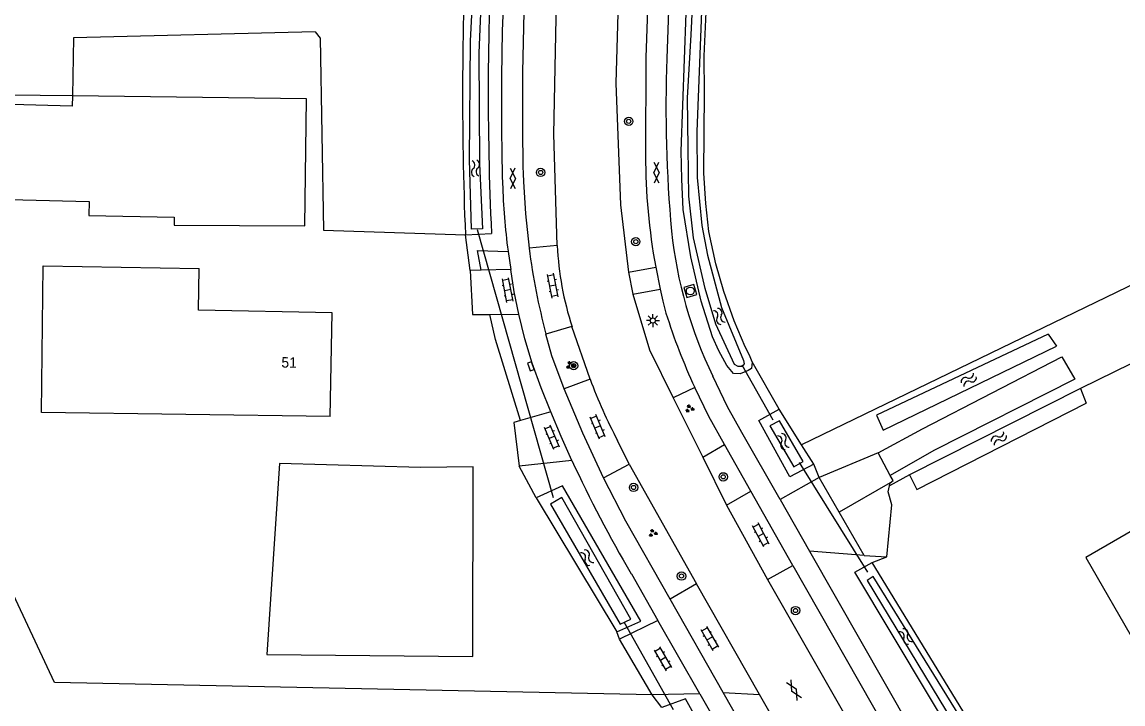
# Model space of a CAD drawing. Extents: x 134297 to 137000, y 403500 to 406000.
# Drawn here: x 136655.3 to 136760.9, y 403757 to 403822.5 of the extents above; entities that cross this region are included whole.
import ezdxf

# ---------------------------------------------------------------- set-up
doc = ezdxf.new("R2010")
doc.units = 0
for name, color, linetype in [('gg-afsc-draadraster', 7, 'Continuous'), ('gg-afsc-lijn draadraster', 7, 'Continuous'), ('gg-anno-huisnummerreeks BGT', 7, 'Continuous'), ('gg-bbg-bijgebouw', 7, 'Continuous'), ('gg-bbg-gedigitaliseerde bebouwing', 7, 'Continuous'), ('gg-bbg-hoofdgebouw', 7, 'Continuous'), ('gg-knt-bronhoudergrens', 7, 'Continuous'), ('gg-knt-onverhard', 7, 'Continuous'), ('gg-knt-verharding', 7, 'Continuous'), ('gg-knt-verharding nz', 7, 'Continuous'), ('gg-kntw-bovenkant insteek waterloop', 7, 'Continuous'), ('gg-kntw-waterlijn', 7, 'Continuous'), ('gg-kwrk-duiker nz buis', 7, 'Continuous'), ('gt-grn-groengrens', 7, 'Continuous'), ('gt-grn-vlakafsluiter', 7, 'Continuous'), ('gt-grn-weggrens', 7, 'Continuous'), ('gt-symb-boom', 7, 'Continuous'), ('gt-symb-gesloten verharding', 7, 'Continuous'), ('gt-symb-groenvak', 7, 'Continuous'), ('gt-symb-klinker verharding', 7, 'Continuous'), ('gt-symb-kolk', 7, 'Continuous'), ('gt-symb-lichtmast', 7, 'Continuous'), ('gt-symb-rioolschacht', 7, 'Continuous'), ('gt-symb-watersymbool', 7, 'Continuous')]:
    doc.layers.add(name, color=color, linetype=linetype)

# ---------------------------------------------------------------- blocks, each defined once
blk = doc.blocks.new('gt0-WA')
at = {"layer": 'gt-symb-watersymbool'}
for centre, start, end in [((-0.32, 0.02), 28.0725, 151.9275), ((0.43, 0.42), 208.0725, 331.9275), ((-0.32, -0.43), 28.0725, 151.9275), ((0.43, -0.03), 208.0725, 331.9275)]:
    blk.add_arc(centre, 0.425, start, end, dxfattribs=at)
blk = doc.blocks.new('gt0-KL1')
at = {"layer": 'gt-symb-klinker verharding'}
for p, q in [((-1.15, 0.3), (1.15, 0.3)), ((-1, -0.3), (-1, 0.3)), ((-0.5, 0.3), (-0.5, 0.45)), ((0, -0.3), (0, 0.3)), ((0.5, 0.3), (0.5, 0.45)), ((1, -0.3), (1, 0.3)), ((-1.15, -0.3), (1.15, -0.3)), ((-0.5, -0.45), (-0.5, -0.3)), ((0.5, -0.45), (0.5, -0.3))]:
    blk.add_line(p, q, dxfattribs=at)
blk = doc.blocks.new('gt0-GESVH1')
at = {"layer": 'gt-symb-gesloten verharding'}
for p, q in [((-0.99, -0.26), (0.01, 0.24)), ((0.01, -0.26), (-0.99, 0.24)), ((0.01, 0.24), (1.01, -0.26)), ((1.01, 0.24), (0.01, -0.26))]:
    blk.add_line(p, q, dxfattribs=at)
blk = doc.blocks.new('gt0-BOOM')
at = {"layer": 'gt-symb-boom'}
for radius in [0.4, 0.2]:
    blk.add_circle((0, 0), radius, dxfattribs=at)
blk = doc.blocks.new('gt0-GRVAK')
at = {"layer": 'gt-symb-groenvak'}
for p, q in [((-0.11, 0.19), (-0.23, 0.24)), ((-0.18, 0.15), (0.09, 0.15)), ((-0.09, 0.21), (-0.16, 0.32)), ((-0.05, 0.21), (-0.05, 0.39)), ((0, 0.21), (0.06, 0.32)), ((0.01, 0.19), (0.13, 0.24)), ((0.26, -0.05), (0.2, 0.06)), ((0.3, -0.05), (0.3, 0.13)), ((0.35, -0.05), (0.41, 0.06)), ((-0.24, -0.23), (-0.36, -0.18)), ((-0.32, -0.26), (-0.05, -0.26)), ((-0.23, -0.21), (-0.29, -0.09)), ((-0.18, -0.2), (-0.18, -0.02)), ((-0.14, -0.21), (-0.07, -0.09)), ((-0.12, -0.23), (0, -0.18)), ((0.24, -0.07), (0.12, -0.02)), ((0.17, -0.11), (0.44, -0.11)), ((0.37, -0.07), (0.49, -0.02))]:
    blk.add_line(p, q, dxfattribs=at)
blk = doc.blocks.new('gt0-LMAST')
at = {"layer": 'gt-symb-lichtmast'}
for p, q in [((-0.18, 0.17), (-0.45, 0.44)), ((-0.01, 0.25), (-0.01, 0.62)), ((0.17, 0.17), (0.44, 0.44)), ((-0.26, 0), (-0.63, 0)), ((-0.18, -0.18), (-0.45, -0.45)), ((-0.01, -0.25), (-0.01, -0.63)), ((0.44, -0.45), (0.17, -0.18)), ((0.24, 0), (0.62, 0))]:
    blk.add_line(p, q, dxfattribs=at)
blk.add_circle((-0.01, 0), 0.25, dxfattribs=at)
blk = doc.blocks.new('gt0-RS')
at = {"layer": 'gt-symb-rioolschacht'}
blk.add_lwpolyline([(-0.5, -0.5), (0.5, -0.5), (0.5, 0.5), (-0.5, 0.5)], close=True, dxfattribs=at)
blk.add_circle((0, 0), 0.375, dxfattribs=at)
blk = doc.blocks.new('gt0-KOLK')
at = {"layer": 'gt-symb-kolk'}
blk.add_lwpolyline([(0, 0), (0.38, 0), (0.38, 0.4), (-0.38, 0.4), (-0.38, 0), (0, 0)], dxfattribs=at)

msp = doc.modelspace()

# ---------------------------------------------------------------- linework, layer by layer
at = {"layer": 'gg-afsc-draadraster'}
msp.add_lwpolyline([(136715.77, 403757.91), (136658.46, 403759.09), (136652.16, 403772.51), (136648.44, 403778.54), (136647.3, 403780.85), (136647.28, 403784.23), (136613.81, 403784.54), (136613.66, 403800.45)], dxfattribs=at)
at = {"layer": 'gg-afsc-lijn draadraster'}
msp.add_lwpolyline([(136715.77, 403757.91), (136658.46, 403759.09), (136652.16, 403772.51), (136648.44, 403778.54), (136647.3, 403780.85), (136647.28, 403784.23), (136613.81, 403784.54), (136613.66, 403800.45)], dxfattribs=at)
at = {"layer": 'gg-bbg-bijgebouw'}
msp.add_lwpolyline([(136660.18, 403815.37), (136660.16, 403814.39), (136640.38, 403814.94), (136640.14, 403805.8), (136661.78, 403805.25), (136661.75, 403803.89), (136669.93, 403803.75), (136669.93, 403802.98), (136682.47, 403802.91), (136682.61, 403815.1), (136660.18, 403815.37)], dxfattribs=at)
at = {"layer": 'gg-bbg-gedigitaliseerde bebouwing'}
msp.add_lwpolyline([(136684.88, 403784.61), (136657.21, 403784.99), (136657.38, 403799.06), (136672.32, 403798.83)], dxfattribs=at)
at = {"layer": 'gg-bbg-hoofdgebouw'}
for points in [[(136684.88, 403784.61), (136685.09, 403794.57), (136672.25, 403794.83), (136672.32, 403798.83)], [(136765.89, 403776.04), (136757.34, 403771.09)], [(136757.34, 403771.09), (136762.17, 403762.72)]]:
    msp.add_lwpolyline(points, dxfattribs=at)
at = {"layer": 'gg-knt-bronhoudergrens'}
for p, q in [((136792.85, 403805.05), (136756.81, 403787.3)), ((136716.69, 403756.7), (136715.77, 403757.91))]:
    msp.add_line(p, q, dxfattribs=at)
for points in [[(136859.35, 403844.51), (136842.84, 403836.67), (136782.41, 403807.25), (136730.09, 403781.89)], [(136683.44, 403821.51), (136660.29, 403820.93), (136660.18, 403815.37)], [(136683.44, 403821.51), (136683.93, 403820.9), (136684.26, 403802.49), (136697.85, 403802.03)], [(136660.18, 403815.37), (136613.5, 403815.87), (136613.66, 403800.45)], [(136698.55, 403761.6), (136698.6, 403779.78), (136693.55, 403779.71), (136680.02, 403780.1), (136678.81, 403761.79), (136698.55, 403761.6)]]:
    msp.add_lwpolyline(points, dxfattribs=at)
at = {"layer": 'gg-knt-onverhard'}
for points in [[(136737.41, 403781.13), (136741.69, 403783.43), (136755.04, 403790.34)], [(136756.27, 403788.19), (136742.76, 403781.36), (136738.58, 403778.95)]]:
    msp.add_lwpolyline(points, dxfattribs=at)
at = {"layer": 'gg-knt-verharding'}
for p, q in [((136701.94, 403800.46), (136702.21, 403798.71)), ((136706.66, 403801.02), (136703.95, 403800.76)), ((136699.35, 403798.64), (136698.32, 403798.62)), ((136702.21, 403798.71), (136699.35, 403798.64)), ((136713.5, 403798.47), (136716.1, 403798.95)), ((136713.5, 403798.47), (136713.9, 403796.36)), ((136716.1, 403798.95), (136716.53, 403796.83)), ((136713.9, 403796.36), (136716.53, 403796.83)), ((136700.18, 403794.41), (136702.96, 403794.45)), ((136708.07, 403793.24), (136705.56, 403792.51)), ((136709.8, 403788.21), (136708.07, 403793.24)), ((136709.8, 403788.21), (136707.33, 403787.27)), ((136717.78, 403786.42), (136720.6, 403780.72)), ((136706.04, 403785.05), (136703.14, 403784.24)), ((136713.54, 403780.06), (136712.44, 403782.32)), ((136725.23, 403777.44), (136722.68, 403781.92)), ((136737.41, 403781.13), (136731.78, 403778.78)), ((136738.58, 403778.95), (136737.41, 403781.13)), ((136708.06, 403780.4), (136703.01, 403779.84)), ((136711.08, 403778.75), (136713.54, 403780.06)), ((136713.54, 403780.06), (136720, 403768.55)), ((136720.6, 403780.72), (136722.89, 403776.1)), ((136731.78, 403778.78), (136728.04, 403776.64)), ((136733.7, 403775.44), (136731.78, 403778.78)), ((136738.52, 403777.97), (136738.59, 403778.25)), ((136722.89, 403776.1), (136725.23, 403777.44)), ((136729.23, 403770.34), (136725.23, 403777.44)), ((136722.89, 403776.1), (136726.83, 403768.98)), ((136728.04, 403776.64), (136730.84, 403771.71)), ((136736.09, 403771.29), (136733.7, 403775.44)), ((136736.09, 403771.29), (136730.84, 403771.71)), ((136730.84, 403771.71), (136776.48, 403691.56)), ((136736.09, 403771.29), (136738.25, 403771.14)), ((136713.76, 403769.53), (136716.31, 403765.06)), ((136726.83, 403768.98), (136729.23, 403770.34)), ((136729.23, 403770.34), (136774.89, 403690.26)), ((136720, 403768.55), (136717.47, 403767.09)), ((136726.04, 403757.96), (136720, 403768.55)), ((136726.83, 403768.98), (136773.23, 403687.76)), ((136722.56, 403758.14), (136717.47, 403767.09)), ((136716.31, 403765.06), (136712.62, 403763.27)), ((136720.33, 403758.01), (136716.31, 403765.06)), ((136715.77, 403757.91), (136712.62, 403763.27)), ((136720.33, 403758.01), (136715.77, 403757.91)), ((136720.33, 403758.01), (136726.27, 403747.62)), ((136727.22, 403749.95), (136722.56, 403758.14)), ((136722.56, 403758.14), (136726.04, 403757.96)), ((136729.82, 403751.34), (136726.04, 403757.96))]:
    msp.add_line(p, q, dxfattribs=at)
for points in [[(136721.41, 403912.31), (136717.59, 403830.93), (136717.16, 403818.97)], [(136716.39, 403911.3), (136715.66, 403893.27), (136714.5, 403868.42), (136712.83, 403835.52), (136712.27, 403816.6), (136712.72, 403804.92), (136713.5, 403798.47)], [(136719.32, 403911.12), (136715.57, 403830.99), (136715.14, 403819.05), (136715.13, 403809.67)], [(136706.66, 403801.02), (136706.33, 403811.7), (136706.78, 403834.02), (136708.07, 403859.85), (136709.6, 403889.61), (136710.13, 403901.36)], [(136703.41, 403807.16), (136703.6, 403804.05), (136703.95, 403800.76)], [(136698.32, 403798.62), (136698.53, 403794.4), (136700.18, 403794.41)], [(136702.96, 403794.45), (136702.54, 403796.57), (136702.21, 403798.71)], [(136713.9, 403796.36), (136715.5, 403791), (136717.78, 403786.42)], [(136716.53, 403796.83), (136716.79, 403795.68), (136717.08, 403794.54)], [(136706.04, 403785.05), (136705.12, 403787.38), (136704.24, 403789.73), (136703.54, 403792.07), (136702.96, 403794.45)], [(136707.33, 403787.27), (136706.14, 403790.43), (136705.56, 403792.51)], [(136728.04, 403776.64), (136724.35, 403783.09), (136722.99, 403785.54), (136721.57, 403788.48)], [(136722.68, 403781.92), (136721.19, 403784.63), (136719.84, 403787.41)], [(136711.08, 403778.75), (136709.1, 403783.01), (136707.33, 403787.27)], [(136703.14, 403784.24), (136702.48, 403784.05), (136703.01, 403779.84)], [(136708.06, 403780.4), (136707.03, 403782.71), (136706.04, 403785.05)], [(136738.59, 403778.25), (136738.85, 403778.47), (136738.58, 403778.95)], [(136717.47, 403767.09), (136713.22, 403774.58), (136711.08, 403778.75)], [(136738.74, 403776.15), (136738.39, 403777.4), (136738.52, 403777.97)]]:
    msp.add_lwpolyline(points, dxfattribs=at)
for centre, radius, start, end in [((136971.2, 403814.58), 269.9, 176.6428, 181.6149), ((136967.96, 403814.36), 264.65, 176.5525, 181.5588), ((136852.84, 403814.37), 135.76, 178.0569, 185.0551), ((136775.43, 403809.74), 60.31, 180.0674, 190.3118), ((136760.94, 403808.57), 59.55, 181.5356, 187.8242), ((136759.12, 403806.7), 41.73, 185.9058, 205.8839), ((136769.79, 403809.34), 66.39, 187.4264, 194.6855), ((136736.45, 403802.41), 29.82, 182.6771, 197.9196), ((136777.17, 403813.71), 63.08, 197.6933, 204.64), ((136753.2, 403804.11), 46.22, 200.1259, 208.1378), ((136817.02, 403830.52), 119.93, 204.7017, 210.5698)]:
    msp.add_arc(centre, radius, start, end, dxfattribs=at)
at = {"layer": 'gg-knt-verharding nz'}
msp.add_line((136738.59, 403778.25), (136733.7, 403775.44), dxfattribs=at)
at = {"layer": 'gg-kntw-bovenkant insteek waterloop'}
for p, q in [((136720.73, 403819.19), (136724.79, 403908.84)), ((136697.85, 403802.03), (136700.34, 403802.18)), ((136753.71, 403792.51), (136754.52, 403791.35)), ((136756.81, 403787.3), (136740.43, 403779.01)), ((136756.81, 403787.3), (136757.38, 403785.91)), ((136730.09, 403781.89), (136727.93, 403785.31)), ((136731.26, 403780.03), (136730.09, 403781.89)), ((136704.64, 403776.83), (136712.38, 403763.96)), ((136773.06, 403711.41), (136736.85, 403770.62))]:
    msp.add_line(p, q, dxfattribs=at)
for points in [[(136725.33, 403789.87), (136725.27, 403789.21), (136724.96, 403789.03), (136724.19, 403788.7), (136723.56, 403788.74), (136722.93, 403789.51), (136722.14, 403790.93), (136721.55, 403792.25), (136720.46, 403795.69), (136719.48, 403799.92), (136718.74, 403804.48), (136718.59, 403807.4), (136718.55, 403810.07), (136719.19, 403827.75), (136720.59, 403862.43), (136722.55, 403909.1), (136724.79, 403908.84)], [(136725.33, 403789.87), (136725.08, 403790.5), (136724.67, 403791.31), (136723.62, 403793.79), (136722.63, 403796.6), (136721.85, 403799.27), (136721.19, 403802.35), (136720.91, 403805.04), (136720.72, 403807.96), (136720.79, 403815.68), (136720.73, 403819.19)], [(136753.71, 403792.51), (136737.26, 403784.74), (136737.9, 403783.31), (136754.52, 403791.35)], [(136731.26, 403780.03), (136728.96, 403778.83), (136725.99, 403784.25), (136727.93, 403785.31)], [(136740.43, 403779.01), (136741.12, 403777.63), (136757.38, 403785.91)], [(136712.38, 403763.96), (136714.68, 403764.98), (136707.17, 403777.97), (136704.64, 403776.83)], [(136770.71, 403710.36), (136735.2, 403769.68), (136736.85, 403770.62)], [(136721.62, 403747.83), (136723.64, 403749.06), (136718.94, 403757.52), (136716.69, 403756.7)]]:
    msp.add_lwpolyline(points, dxfattribs=at)
for centre, radius, start, end in [((137024.36, 403815.32), 326.78, 176.9586, 182.3305), ((136998.83, 403815.71), 298.79, 176.8644, 182.5947)]:
    msp.add_arc(centre, radius, start, end, dxfattribs=at)
at = {"layer": 'gg-kntw-waterlijn'}
for points in [[(136723.76, 403897.15), (136722.29, 403869.58), (136720.03, 403811.97), (136720.07, 403807.54), (136720.53, 403802.93), (136721.05, 403800.08), (136722.39, 403795.09), (136724.51, 403790), (136724.57, 403789.68), (136724.38, 403789.43), (136724, 403789.4), (136723.64, 403789.6), (136721.87, 403793.46), (136720.84, 403796.91), (136719.72, 403801.77), (136719.28, 403805.76), (136719.21, 403810.35), (136719.13, 403815.19), (136719.5, 403821.23), (136720.27, 403836.93), (136723.22, 403908.16), (136724.21, 403908.11), (136723.76, 403897.15)], [(136698.42, 403802.6), (136698.25, 403809.26), (136698.35, 403820.64), (136702.6, 403902.6), (136703.67, 403902.54), (136702.34, 403883.74), (136700.88, 403852.52), (136699.76, 403833.95), (136699.14, 403819.49), (136699.2, 403808.86), (136699.49, 403802.61), (136698.42, 403802.6)], [(136727.04, 403783.72), (136729.33, 403779.78), (136730.24, 403780.31), (136727.97, 403784.2), (136727.04, 403783.72)], [(136706, 403776.21), (136712.7, 403764.71), (136713.71, 403765.17), (136707.09, 403776.84), (136706, 403776.21)], [(136736.37, 403768.88), (136752.13, 403742.87), (136760.69, 403728.96), (136771.19, 403711.08), (136771.85, 403711.47), (136757.42, 403735.78), (136746.08, 403754.48), (136736.96, 403769.26), (136736.37, 403768.88)]]:
    msp.add_lwpolyline(points, dxfattribs=at)
at = {"layer": 'gg-kwrk-duiker nz buis'}
for p, q in [((136706.31, 403776.8), (136699.02, 403802.52)), ((136724.35, 403789.56), (136727.33, 403784.29)), ((136736.45, 403769.68), (136729.89, 403780.22)), ((136717.81, 403756.47), (136713.07, 403764.89))]:
    msp.add_line(p, q, dxfattribs=at)
at = {"layer": 'gt-grn-groengrens'}
for p, q in [((136698.32, 403798.62), (136697.85, 403802.03)), ((136719.84, 403787.41), (136717.78, 403786.42)), ((136720.6, 403780.72), (136722.68, 403781.92)), ((136731.78, 403778.78), (136731.26, 403780.03)), ((136704.64, 403776.83), (136703.01, 403779.84)), ((136736.85, 403770.62), (136738.25, 403771.14)), ((136712.62, 403763.27), (136712.38, 403763.96))]:
    msp.add_line(p, q, dxfattribs=at)
for points in [[(136699.35, 403798.64), (136699.01, 403800.55), (136701.94, 403800.46)], [(136703.14, 403784.24), (136700.75, 403791.99), (136700.18, 403794.41)]]:
    msp.add_lwpolyline(points, dxfattribs=at)
at = {"layer": 'gt-grn-vlakafsluiter'}
for p, q in [((136727.93, 403785.31), (136725.33, 403789.87)), ((136740.43, 403779.01), (136738.52, 403777.97)), ((136738.25, 403771.14), (136738.74, 403776.15))]:
    msp.add_line(p, q, dxfattribs=at)
at = {"layer": 'gt-grn-weggrens'}
msp.add_line((136755.04, 403790.34), (136756.27, 403788.19), dxfattribs=at)

# ---------------------------------------------------------------- block references
at = {"layer": 'gt-symb-boom'}
for p in [(136713.51, 403812.93), (136705.06, 403808.03), (136714.19, 403801.39), (136708.23, 403789.49), (136722.57, 403778.83), (136713.97, 403777.81), (136718.57, 403769.31), (136729.5, 403766)]:
    msp.add_blockref('gt0-BOOM', p, dxfattribs=at)
at = {"layer": 'gt-symb-gesloten verharding'}
for p, rotation in [((136716.16, 403808), 90.97393443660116), ((136702.39, 403807.45), 90.97393443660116), ((136729.36, 403758.38), -59.99927221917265)]:
    msp.add_blockref('gt0-GESVH1', p, dxfattribs=dict(at, rotation=rotation))
at = {"layer": 'gt-symb-groenvak'}
for p in [(136707.89, 403789.54), (136719.34, 403785.37), (136715.82, 403773.43)]:
    msp.add_blockref('gt0-GRVAK', p, dxfattribs=at)
at = {"layer": 'gt-symb-klinker verharding'}
for p, rotation in [((136701.91, 403796.74), 101.00666417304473), ((136706.23, 403797.17), 101.00666417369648), ((136710.54, 403783.62), 113.02549200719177), ((136706.16, 403782.62), 113.02549200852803), ((136726.18, 403773.26), 117.97472992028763), ((136721.27, 403763.33), -60.205382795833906), ((136716.81, 403761.37), 120.00072778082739)]:
    msp.add_blockref('gt0-KL1', p, dxfattribs=dict(at, rotation=rotation))
at = {"layer": 'gt-symb-kolk', "rotation": -70.96692019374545}
msp.add_blockref('gt0-KOLK', (136703.94, 403789.37), dxfattribs=at)
at = {"layer": 'gt-symb-lichtmast'}
msp.add_blockref('gt0-LMAST', (136715.83, 403793.82), dxfattribs=at)
at = {"layer": 'gt-symb-rioolschacht', "rotation": 16.02410965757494}
msp.add_blockref('gt0-RS', (136719.41, 403796.66), dxfattribs=at)
at = {"layer": 'gt-symb-watersymbool'}
for p, rotation in [((136698.82, 403808.37), 97.99231392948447), ((136722.21, 403794.17), 118.99897714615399), ((136746.15, 403788.17), -141.98433951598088), ((136749.05, 403782.54), -141.98433951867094), ((136728.36, 403782.16), 118.99897714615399), ((136709.55, 403771.03), 126.9958977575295), ((136740.1, 403763.46), 126.9958977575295)]:
    msp.add_blockref('gt0-WA', p, dxfattribs=dict(at, rotation=rotation))

# ---------------------------------------------------------------- texts
at = {"layer": 'gg-anno-huisnummerreeks BGT'}
msp.add_text('51', height=1, rotation=358.8, dxfattribs=at).set_placement((136680.2, 403789.32))

doc.saveas('drawing.dxf')
